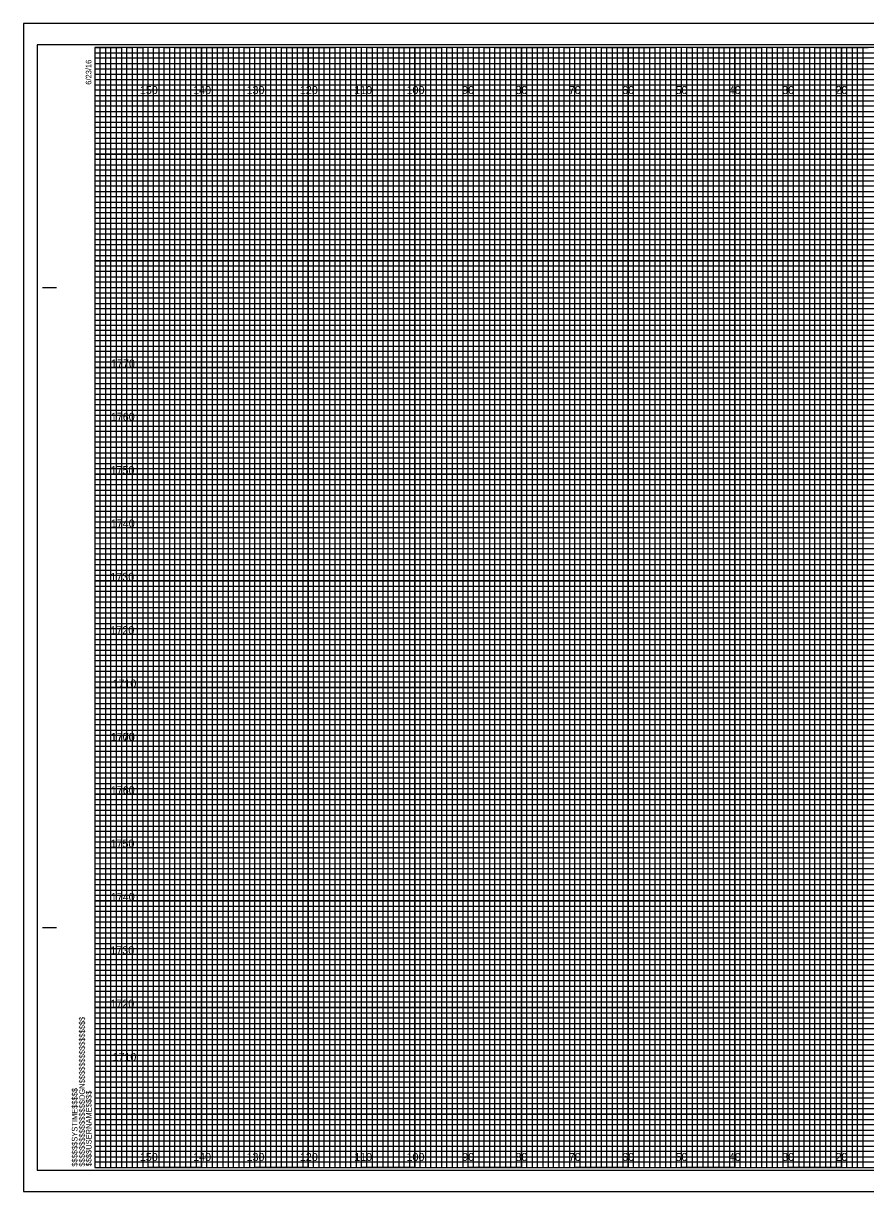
# Model space of a CAD drawing. Extents: x -419 to 4739, y -630 to 13534.
# Drawn here: x 476.2 to 634.1, y 4608 to 4827 of the extents above; entities that cross this region are included whole.
import ezdxf

# ---------------------------------------------------------------- set-up
doc = ezdxf.new("R2010")
doc.units = 0
for name, color, linetype in [('Old_Level_62', 7, 'Continuous'), ('Pattern 1', 7, 'Continuous'), ('Pattern 18', 7, 'Continuous'), ('Pattern 4', 7, 'Continuous'), ('Pattern 5', 7, 'Continuous'), ('Prop Dimension', 7, 'Continuous'), ('Prop Horizontal Alignment', 7, 'Continuous'), ('Raster_Level_0', 7, 'Continuous'), ('Scratch_Level_0', 7, 'Continuous'), ('Scratch_Level_3', 7, 'Continuous'), ('Scratch_Level_5', 7, 'Continuous')]:
    doc.layers.add(name, color=color, linetype=linetype)

msp = doc.modelspace()

# ---------------------------------------------------------------- linework, layer by layer
at = {"layer": 'Old_Level_62'}
for p, q in [((479.78, 4777.54), (482.28, 4777.54)), ((479.88, 4777.54), (482.38, 4777.54)), ((479.78, 4657.54), (482.28, 4657.54)), ((479.88, 4657.54), (482.38, 4657.54)), ((489.58, 4612.54), (489.58, 4612.54)), ((489.58, 4612.54), (489.58, 4612.54)), ((489.58, 4612.54), (489.58, 4612.54)), ((489.58, 4612.54), (489.58, 4612.54)), ((489.58, 4612.54), (489.58, 4612.54)), ((489.58, 4612.54), (489.58, 4612.54)), ((489.58, 4612.54), (489.58, 4612.54))]:
    msp.add_line(p, q, dxfattribs=at)
msp.add_lwpolyline([(809.58, 4822.54), (489.58, 4822.54), (489.58, 4612.54), (809.58, 4612.54)], close=True, dxfattribs=at)
at = {"layer": 'Pattern 18'}
msp.add_lwpolyline([(476.18, 4608.04), (812.88, 4608.04), (812.88, 4827.04), (476.18, 4827.04)], close=True, dxfattribs=at)
at = {"layer": 'Pattern 4'}
for p, q in [((489.58, 4821.54), (749.58, 4821.54)), ((749.58, 4820.52), (489.58, 4820.52)), ((489.58, 4820.52), (489.58, 4819.54)), ((489.58, 4819.54), (749.58, 4819.54)), ((749.58, 4818.43), (489.58, 4818.43)), ((489.58, 4818.43), (489.58, 4816.54)), ((489.58, 4816.54), (809.58, 4816.54))]:
    msp.add_line(p, q, dxfattribs=at)
for points in [[(489.58, 4815.54), (759.58, 4815.54), (809.58, 4815.54), (809.58, 4814.54), (489.58, 4814.54)], [(489.58, 4813.54), (809.58, 4813.54), (809.58, 4811.54), (489.58, 4811.54)], [(489.58, 4810.54), (809.58, 4810.54), (809.58, 4809.54), (489.58, 4809.52)], [(489.58, 4808.54), (809.58, 4808.54), (809.58, 4806.54), (489.58, 4806.54)], [(489.58, 4805.54), (809.58, 4805.54), (809.58, 4804.54), (489.58, 4804.54)], [(489.58, 4803.54), (809.58, 4803.54), (809.58, 4801.54), (489.58, 4801.54)], [(489.58, 4800.54), (809.58, 4800.54), (809.58, 4799.54), (489.58, 4799.54)], [(489.58, 4798.54), (809.58, 4798.54), (809.58, 4796.54), (489.58, 4796.54)], [(489.58, 4795.54), (809.58, 4795.54), (809.58, 4794.54), (489.58, 4794.54)], [(489.58, 4793.54), (809.58, 4793.54), (809.58, 4791.54), (489.58, 4791.54)], [(489.58, 4790.54), (809.58, 4790.54), (809.58, 4789.54), (489.58, 4789.54)], [(489.58, 4788.54), (809.58, 4788.54), (809.58, 4786.49), (809.58, 4785.54), (809.58, 4784.54), (489.58, 4784.54)], [(489.58, 4786.54), (809.58, 4786.54), (809.58, 4785.54), (489.58, 4785.54)], [(489.58, 4783.54), (809.58, 4783.54), (809.58, 4781.54), (489.58, 4781.57)], [(489.58, 4781.57), (809.58, 4781.54), (809.58, 4780.54), (489.58, 4780.54)], [(489.58, 4779.54), (809.58, 4779.54), (809.58, 4778.54), (489.58, 4778.54)], [(489.58, 4776.54), (809.58, 4776.54), (809.58, 4775.54), (489.58, 4775.54)], [(489.58, 4774.54), (809.58, 4774.54), (809.58, 4773.54), (489.58, 4773.54)], [(489.51, 4771.43), (809.58, 4771.43), (809.58, 4770.42), (489.51, 4770.42)], [(489.58, 4769.54), (809.58, 4769.54), (809.58, 4768.54), (489.58, 4768.54)], [(489.58, 4766.54), (809.58, 4766.54), (809.58, 4765.54), (489.58, 4765.54)], [(489.58, 4764.54), (809.58, 4764.54), (809.58, 4763.54), (489.58, 4763.54)], [(489.58, 4761.54), (809.58, 4761.54), (809.58, 4760.54), (489.58, 4760.54)], [(489.58, 4759.54), (809.58, 4759.54), (809.58, 4758.54), (489.58, 4758.54)], [(489.58, 4756.54), (809.58, 4756.54), (809.58, 4755.54), (489.58, 4755.54)], [(489.58, 4754.54), (809.58, 4754.54), (809.58, 4753.54), (489.58, 4753.54)], [(489.58, 4751.54), (809.58, 4751.54), (809.57, 4750.52), (489.58, 4750.54)], [(489.58, 4749.54), (809.58, 4749.54), (809.58, 4748.54), (489.58, 4748.54)], [(489.58, 4746.54), (809.58, 4746.54), (809.58, 4745.54), (489.58, 4745.54)], [(489.58, 4744.54), (809.58, 4744.54), (809.58, 4743.54), (489.58, 4743.54)], [(489.58, 4741.54), (809.58, 4741.54), (809.58, 4740.54), (489.58, 4740.54)], [(489.58, 4739.54), (809.58, 4739.54), (809.58, 4738.54), (489.58, 4738.54)], [(489.58, 4736.54), (809.58, 4736.54), (809.58, 4735.54), (489.58, 4735.54)], [(489.58, 4734.54), (809.58, 4734.54), (809.58, 4733.54), (489.58, 4733.54)], [(489.58, 4731.54), (809.58, 4731.54), (809.58, 4730.54), (489.58, 4730.54)], [(489.58, 4729.53), (809.65, 4729.45), (809.58, 4728.54), (489.58, 4728.54)], [(489.58, 4726.54), (809.58, 4726.54), (809.58, 4725.54), (489.58, 4725.54)], [(489.58, 4724.54), (809.58, 4724.54), (809.58, 4723.54), (489.58, 4723.54)], [(489.58, 4721.54), (809.58, 4721.54), (809.58, 4720.54), (489.58, 4720.54)], [(489.58, 4719.54), (809.58, 4719.54), (809.58, 4718.54), (489.58, 4718.54)], [(489.58, 4716.54), (809.58, 4716.54), (809.58, 4715.54), (489.58, 4715.54)], [(489.58, 4714.54), (809.58, 4714.54), (809.58, 4713.54), (489.58, 4713.54)], [(489.58, 4711.54), (809.58, 4711.54), (809.58, 4710.54), (489.58, 4710.54)], [(489.58, 4709.54), (809.58, 4709.54), (809.58, 4708.54), (489.58, 4708.54)], [(489.58, 4706.54), (809.58, 4706.54), (809.58, 4705.54), (489.58, 4705.54)], [(489.58, 4704.54), (809.58, 4704.54), (809.58, 4703.54), (489.58, 4703.54)], [(489.58, 4701.54), (809.58, 4701.54), (809.58, 4700.54), (489.58, 4700.54)], [(489.58, 4699.54), (809.58, 4699.54), (809.58, 4698.54), (489.58, 4698.54)], [(489.58, 4696.54), (809.58, 4696.54), (809.58, 4695.54), (489.58, 4695.54)], [(489.58, 4694.54), (809.58, 4694.54), (809.58, 4693.54), (489.58, 4693.54)], [(489.58, 4691.54), (809.58, 4691.54), (809.57, 4690.52), (489.58, 4690.54)], [(489.58, 4689.54), (809.58, 4689.54), (809.58, 4688.54), (489.58, 4688.54)], [(489.58, 4686.54), (809.58, 4686.54), (809.58, 4685.54), (489.58, 4685.54)], [(489.58, 4684.54), (809.58, 4684.54), (809.58, 4683.54), (489.58, 4683.54)], [(489.58, 4681.54), (809.58, 4681.54), (809.58, 4680.54), (489.58, 4680.54)], [(489.58, 4679.54), (809.58, 4679.54), (809.58, 4678.54), (489.58, 4678.54)], [(489.58, 4676.54), (809.58, 4676.54), (809.58, 4675.54), (489.58, 4675.54)], [(489.58, 4674.54), (809.58, 4674.54), (809.58, 4673.54), (489.58, 4673.54)], [(489.58, 4671.54), (809.58, 4671.54), (809.58, 4670.54), (489.58, 4670.54)], [(489.58, 4669.53), (809.65, 4669.45), (809.58, 4668.54), (489.58, 4668.54)], [(489.58, 4666.54), (809.58, 4666.54), (809.58, 4665.54), (489.58, 4665.54)], [(489.58, 4664.54), (809.58, 4664.54), (809.58, 4663.54), (489.58, 4663.54)], [(489.58, 4661.54), (809.58, 4661.54), (809.58, 4660.54), (489.58, 4660.54)], [(489.58, 4659.54), (809.58, 4659.54), (809.58, 4658.54), (489.58, 4658.54)], [(489.58, 4656.54), (809.58, 4656.54), (809.58, 4655.54), (489.58, 4655.54)], [(489.58, 4654.54), (809.58, 4654.54), (809.58, 4653.54), (489.58, 4653.54)], [(489.58, 4651.54), (809.58, 4651.54), (809.58, 4650.54), (489.58, 4650.54)], [(489.58, 4649.54), (809.58, 4649.54), (809.58, 4648.54), (489.58, 4648.54)], [(489.58, 4646.54), (809.58, 4646.54), (809.58, 4645.54), (489.58, 4645.54)], [(489.58, 4644.54), (809.58, 4644.54), (809.58, 4643.54), (489.58, 4643.54)], [(489.58, 4641.54), (809.58, 4641.54), (809.58, 4640.54), (489.58, 4640.54)], [(489.58, 4639.54), (809.58, 4639.54), (809.58, 4638.54), (489.58, 4638.54)], [(489.58, 4636.54), (809.58, 4636.54), (809.58, 4635.54), (489.58, 4635.54)], [(489.58, 4634.54), (809.58, 4634.54), (809.58, 4633.54), (489.58, 4633.54)], [(489.58, 4631.54), (809.58, 4631.54), (809.58, 4630.54), (489.58, 4630.54)], [(489.58, 4629.54), (809.58, 4629.54), (809.58, 4628.54), (489.58, 4628.54)], [(489.58, 4626.54), (809.58, 4626.54), (809.58, 4625.54), (489.58, 4625.54)], [(489.58, 4624.54), (809.58, 4624.54), (809.58, 4623.54), (489.58, 4623.54)], [(489.58, 4621.54), (809.58, 4621.54), (809.58, 4620.54), (489.58, 4620.54)], [(489.58, 4619.54), (809.58, 4619.54), (809.58, 4618.54), (489.58, 4618.54)], [(489.58, 4616.54), (809.58, 4616.54), (809.58, 4615.54), (489.58, 4615.54)], [(489.58, 4614.54), (809.58, 4614.54), (809.58, 4613.54), (489.58, 4613.54)]]:
    msp.add_lwpolyline(points, dxfattribs=at)
at = {"layer": 'Pattern 5'}
for p, q in [((812.88, 4827.04), (476.18, 4827.04)), ((476.18, 4827.04), (476.18, 4608.04)), ((476.18, 4608.04), (812.88, 4608.04))]:
    msp.add_line(p, q, dxfattribs=at)
at = {"layer": 'Prop Dimension'}
for points in [[(489.58, 4612.54), (490.58, 4612.54), (490.58, 4822.54), (491.58, 4822.54), (491.58, 4612.54)], [(491.58, 4612.54), (492.58, 4612.54), (492.58, 4822.54), (493.58, 4822.54), (493.58, 4612.54)], [(494.58, 4612.54), (495.58, 4612.54), (495.58, 4822.54), (496.58, 4822.54), (496.58, 4612.54)], [(496.58, 4612.54), (497.58, 4612.54), (497.58, 4822.54), (498.58, 4822.54), (498.58, 4612.54)], [(499.58, 4612.54), (500.58, 4612.54), (500.58, 4822.54), (501.58, 4822.54), (501.58, 4612.54)], [(501.58, 4612.54), (502.58, 4612.54), (502.58, 4822.54), (503.58, 4822.54), (503.58, 4612.54)], [(504.58, 4612.54), (505.58, 4612.54), (505.58, 4822.54), (506.58, 4822.54), (506.58, 4612.54)], [(506.58, 4612.54), (507.58, 4612.54), (507.58, 4822.54), (508.58, 4822.54), (508.58, 4612.54)], [(509.58, 4612.54), (510.58, 4612.54), (510.58, 4822.54), (511.58, 4822.54), (511.58, 4612.54)], [(511.58, 4612.54), (512.58, 4612.54), (512.58, 4822.54), (513.58, 4822.54), (513.58, 4612.54)], [(514.58, 4612.54), (515.58, 4612.54), (515.58, 4822.54), (516.58, 4822.54), (516.58, 4612.54)], [(516.58, 4612.54), (517.58, 4612.54), (517.58, 4822.54), (518.58, 4822.54), (518.58, 4612.54)], [(519.58, 4612.54), (520.58, 4612.54), (520.58, 4822.54), (521.58, 4822.54), (521.58, 4612.54)], [(521.58, 4612.54), (522.58, 4612.54), (522.58, 4822.54), (523.58, 4822.54), (523.58, 4612.54)], [(524.58, 4612.54), (525.58, 4612.54), (525.58, 4822.54), (526.58, 4822.54), (526.58, 4612.54)], [(526.58, 4612.54), (527.58, 4612.54), (527.58, 4822.54), (528.58, 4822.54), (528.58, 4612.54)], [(529.58, 4612.54), (530.58, 4612.54), (530.58, 4822.54), (531.58, 4822.54), (531.58, 4612.54)], [(531.58, 4612.54), (532.58, 4612.54), (532.58, 4822.54), (533.58, 4822.54), (533.58, 4612.54)], [(534.58, 4612.54), (535.58, 4612.54), (535.58, 4822.54), (536.58, 4822.54), (536.58, 4612.54)], [(536.58, 4612.54), (537.58, 4612.54), (537.58, 4822.54), (538.58, 4822.54), (538.58, 4612.54)], [(539.58, 4612.54), (540.58, 4612.54), (540.58, 4822.54), (541.58, 4822.54), (541.58, 4612.54)], [(541.58, 4612.54), (542.58, 4612.54), (542.58, 4822.54), (543.58, 4822.54), (543.58, 4612.54)], [(544.58, 4612.54), (545.58, 4612.54), (545.58, 4822.54), (546.58, 4822.54), (546.58, 4612.54)], [(546.58, 4612.54), (547.58, 4612.54), (547.58, 4822.54), (548.58, 4822.54), (548.58, 4612.54)], [(549.58, 4612.54), (550.58, 4612.54), (550.58, 4822.54), (551.58, 4822.54), (551.58, 4612.54)], [(551.58, 4612.54), (552.58, 4612.54), (552.58, 4822.54), (553.58, 4822.54), (553.58, 4612.54)], [(554.58, 4612.54), (555.58, 4612.54), (555.58, 4822.54), (556.58, 4822.54), (556.58, 4612.54)], [(556.58, 4612.54), (557.58, 4612.54), (557.58, 4822.54), (558.58, 4822.54), (558.58, 4612.54)], [(559.58, 4612.54), (560.58, 4612.54), (560.58, 4822.54), (561.58, 4822.54), (561.58, 4612.54)], [(561.58, 4612.54), (562.58, 4612.54), (562.58, 4822.54), (563.58, 4822.54), (563.58, 4612.54)], [(564.58, 4612.54), (565.58, 4612.54), (565.58, 4822.54), (566.58, 4822.54), (566.58, 4612.54)], [(566.58, 4612.54), (567.58, 4612.54), (567.58, 4822.54), (568.58, 4822.54), (568.58, 4612.54)], [(569.58, 4612.54), (570.58, 4612.54), (570.58, 4822.54), (571.58, 4822.54), (571.58, 4612.54)], [(571.58, 4612.54), (572.58, 4612.54), (572.58, 4822.54), (573.58, 4822.54), (573.58, 4612.54)], [(574.58, 4612.54), (575.58, 4612.54), (575.58, 4822.54), (576.58, 4822.54), (576.58, 4612.54)], [(576.58, 4612.54), (577.58, 4612.54), (577.58, 4822.54), (578.58, 4822.54), (578.58, 4612.54)], [(579.58, 4612.54), (580.58, 4612.54), (580.58, 4822.54), (581.58, 4822.54), (581.58, 4612.54)], [(581.58, 4612.54), (582.58, 4612.54), (582.58, 4822.54), (583.58, 4822.54), (583.58, 4612.54)], [(584.58, 4612.54), (585.58, 4612.54), (585.58, 4822.54), (586.58, 4822.54), (586.58, 4612.54)], [(586.58, 4612.54), (587.58, 4612.54), (587.58, 4822.54), (588.58, 4822.54), (588.58, 4612.54)], [(589.58, 4612.54), (590.58, 4612.54), (590.58, 4822.54), (591.58, 4822.54), (591.58, 4612.54)], [(591.58, 4612.54), (592.58, 4612.54), (592.58, 4822.54), (593.58, 4822.54), (593.58, 4612.54)], [(594.58, 4612.54), (595.58, 4612.54), (595.58, 4822.54), (596.58, 4822.54), (596.58, 4612.54)], [(596.58, 4612.54), (597.58, 4612.54), (597.58, 4822.54), (598.58, 4822.54), (598.58, 4612.54)], [(599.58, 4612.54), (600.58, 4612.54), (600.58, 4822.54), (601.58, 4822.54), (601.58, 4612.54)], [(601.58, 4612.54), (602.58, 4612.54), (602.58, 4822.54), (603.58, 4822.54), (603.58, 4612.54)], [(604.58, 4612.54), (605.58, 4612.54), (605.58, 4822.54), (606.58, 4822.54), (606.58, 4612.54)], [(606.58, 4612.54), (607.58, 4612.54), (607.58, 4822.54), (608.58, 4822.54), (608.58, 4612.54)], [(609.58, 4612.54), (610.58, 4612.54), (610.58, 4822.54), (611.58, 4822.54), (611.58, 4612.54)], [(611.58, 4612.54), (612.58, 4612.54), (612.58, 4822.54), (613.58, 4822.54), (613.58, 4612.54)], [(614.58, 4612.54), (615.58, 4612.54), (615.58, 4822.54), (616.58, 4822.54), (616.58, 4612.54)], [(616.58, 4612.54), (617.58, 4612.54), (617.58, 4822.54), (618.58, 4822.54), (618.58, 4612.54)], [(619.58, 4612.54), (620.58, 4612.54), (620.58, 4822.54), (621.58, 4822.54), (621.58, 4612.54)], [(621.58, 4612.54), (622.58, 4612.54), (622.58, 4822.54), (623.58, 4822.54), (623.58, 4612.54)], [(624.58, 4612.54), (625.58, 4612.54), (625.58, 4822.54), (626.58, 4822.54), (626.58, 4612.54)], [(626.58, 4612.54), (627.58, 4612.54), (627.58, 4822.54), (628.58, 4822.54), (628.58, 4612.54)], [(629.58, 4612.54), (630.58, 4612.54), (630.58, 4822.54), (631.58, 4822.54), (631.58, 4612.54)], [(631.58, 4612.54), (632.58, 4612.54), (632.58, 4822.54), (633.58, 4822.54), (633.58, 4612.54)]]:
    msp.add_lwpolyline(points, dxfattribs=at)
at = {"layer": 'Prop Horizontal Alignment'}
for points in [[(489.58, 4822.54), (494.58, 4822.54), (494.58, 4612.54), (504.58, 4612.54), (504.58, 4822.54), (514.58, 4822.54), (514.58, 4612.54), (524.58, 4612.54), (524.58, 4822.54), (534.58, 4822.54), (534.58, 4612.54), (544.58, 4612.54), (544.58, 4822.54), (554.58, 4822.54), (554.58, 4612.54), (564.58, 4612.54), (564.58, 4822.54), (574.58, 4822.54), (574.58, 4612.54), (584.58, 4612.54), (584.58, 4822.54), (594.58, 4822.54), (594.58, 4612.54), (604.58, 4612.54), (604.58, 4822.54), (614.58, 4822.54), (614.58, 4612.54), (624.58, 4612.54), (624.58, 4822.54), (634.58, 4822.54)], [(489.58, 4817.54), (764.58, 4817.54)], [(489.58, 4797.54), (809.58, 4797.54), (809.58, 4807.54), (489.58, 4807.54)], [(489.58, 4777.54), (809.58, 4777.54), (809.58, 4787.54), (489.58, 4787.54)], [(489.58, 4757.54), (809.58, 4757.54), (809.58, 4767.54), (489.58, 4767.54)], [(489.58, 4737.54), (809.58, 4737.54), (809.58, 4747.54), (489.58, 4747.54)], [(489.58, 4717.54), (809.58, 4717.54), (809.58, 4727.54), (489.58, 4727.54)], [(489.58, 4697.54), (809.58, 4697.54), (809.58, 4707.54), (489.58, 4707.54)], [(489.58, 4677.54), (809.58, 4677.54), (809.58, 4687.54), (489.58, 4687.54)], [(489.58, 4657.54), (809.58, 4657.54), (809.58, 4667.54), (489.58, 4667.54)], [(489.58, 4637.54), (809.58, 4637.54), (809.58, 4647.54), (489.58, 4647.54)], [(489.58, 4617.54), (809.58, 4617.54), (809.58, 4627.54), (489.58, 4627.54)]]:
    msp.add_lwpolyline(points, dxfattribs=at)
at = {"layer": 'Scratch_Level_0'}
for p, q in [((499.58, 4612.54), (499.58, 4822.54)), ((509.58, 4612.54), (509.58, 4822.54)), ((519.58, 4612.54), (519.58, 4822.54)), ((529.58, 4612.54), (529.58, 4822.54)), ((539.58, 4612.54), (539.58, 4822.54)), ((549.58, 4612.54), (549.58, 4822.54)), ((559.58, 4612.54), (559.58, 4822.54)), ((569.58, 4612.54), (569.58, 4822.54)), ((579.58, 4612.54), (579.58, 4822.54)), ((589.58, 4612.54), (589.58, 4822.54)), ((599.58, 4612.54), (599.58, 4822.54)), ((609.58, 4612.54), (609.58, 4822.54)), ((619.58, 4612.54), (619.58, 4822.54)), ((629.58, 4612.54), (629.58, 4822.54)), ((489.58, 4812.54), (809.58, 4812.54)), ((489.58, 4802.54), (809.58, 4802.54)), ((489.58, 4792.54), (809.58, 4792.54)), ((489.58, 4782.54), (809.58, 4782.54)), ((489.58, 4772.54), (809.58, 4772.54)), ((489.58, 4762.54), (809.58, 4762.54)), ((489.58, 4752.54), (809.58, 4752.54)), ((489.58, 4742.54), (809.58, 4742.54)), ((489.58, 4732.54), (809.58, 4732.54)), ((489.58, 4722.54), (809.58, 4722.54)), ((489.58, 4712.54), (809.58, 4712.54)), ((489.58, 4702.54), (809.58, 4702.54)), ((489.58, 4692.54), (809.58, 4692.54)), ((489.58, 4682.54), (809.58, 4682.54)), ((489.58, 4672.54), (809.58, 4672.54)), ((489.58, 4662.54), (809.58, 4662.54)), ((489.58, 4652.54), (809.58, 4652.54)), ((489.58, 4642.54), (809.58, 4642.54)), ((489.58, 4632.54), (809.58, 4632.54)), ((489.58, 4622.54), (809.58, 4622.54))]:
    msp.add_line(p, q, dxfattribs=at)
at = {"layer": 'Scratch_Level_3'}
for p, q in [((499.58, 4822.54), (489.58, 4822.54)), ((499.58, 4612.54), (499.58, 4822.54)), ((519.58, 4822.54), (509.58, 4822.54)), ((509.58, 4822.54), (509.58, 4612.54)), ((519.58, 4612.54), (519.58, 4822.54)), ((539.58, 4822.54), (529.58, 4822.54)), ((529.58, 4822.54), (529.58, 4612.54)), ((539.58, 4612.54), (539.58, 4822.54)), ((559.58, 4822.54), (549.58, 4822.54)), ((549.58, 4822.54), (549.58, 4612.54)), ((559.58, 4612.54), (559.58, 4822.54)), ((579.58, 4822.54), (569.58, 4822.54)), ((569.58, 4822.54), (569.58, 4612.54)), ((579.58, 4612.54), (579.58, 4822.54)), ((599.58, 4822.54), (589.58, 4822.54)), ((589.58, 4822.54), (589.58, 4612.54)), ((599.58, 4612.54), (599.58, 4822.54)), ((619.58, 4822.54), (609.58, 4822.54)), ((609.58, 4822.54), (609.58, 4612.54)), ((619.58, 4612.54), (619.58, 4822.54)), ((639.58, 4822.54), (629.58, 4822.54)), ((629.58, 4822.54), (629.58, 4612.54)), ((509.58, 4612.54), (499.58, 4612.54)), ((529.58, 4612.54), (519.58, 4612.54)), ((549.58, 4612.54), (539.58, 4612.54)), ((569.58, 4612.54), (559.58, 4612.54)), ((589.58, 4612.54), (579.58, 4612.54)), ((609.58, 4612.54), (599.58, 4612.54)), ((629.58, 4612.54), (619.58, 4612.54))]:
    msp.add_line(p, q, dxfattribs=at)
for points in [[(489.58, 4812.54), (809.58, 4812.54), (809.58, 4802.54), (489.58, 4802.54)], [(489.58, 4792.54), (809.58, 4792.54), (809.58, 4782.54), (489.58, 4782.54)], [(489.58, 4772.54), (809.58, 4772.54), (809.58, 4762.54), (489.58, 4762.54)], [(489.58, 4752.54), (809.58, 4752.54), (809.58, 4742.54), (489.58, 4742.54)], [(489.58, 4732.54), (809.58, 4732.54), (809.58, 4722.54), (489.58, 4722.54)], [(489.58, 4712.54), (809.58, 4712.54), (809.58, 4702.54), (489.58, 4702.54)], [(489.58, 4692.54), (809.58, 4692.54), (809.58, 4682.54), (489.58, 4682.54)], [(489.58, 4672.54), (809.58, 4672.54), (809.58, 4662.54), (489.58, 4662.54)], [(489.58, 4652.54), (809.58, 4652.54), (809.58, 4642.54), (489.58, 4642.54)], [(489.58, 4632.54), (809.58, 4632.54), (809.58, 4622.54), (489.58, 4622.54)]]:
    msp.add_lwpolyline(points, dxfattribs=at)
at = {"layer": 'Scratch_Level_5'}
msp.add_lwpolyline([(478.78, 4612.04), (811.98, 4612.04), (811.98, 4823.04), (478.78, 4823.04)], close=True, dxfattribs=at)

# ---------------------------------------------------------------- texts
at = {"layer": 'Old_Level_62'}
for s, p in [('6/23/16', (488.93, 4815.54)), ('$$$$$$$$$$$$$$$$DGN$$$$$$$$$$$$$$$$', (487.7, 4612.72)), ('$$$$$$SYSTIME$$$$$', (486.32, 4612.72)), ('$$$$USERNAME$$$$', (488.96, 4612.77))]:
    msp.add_text(s, height=1.05, rotation=90, dxfattribs=at).set_placement(p)
at = {"layer": 'Pattern 1'}
for s, p in [('1770', (492.62, 4762.54)), ('1760', (492.58, 4752.54)), ('1750', (492.53, 4742.54)), ('1740', (492.58, 4732.54)), ('1730', (492.5, 4722.54)), ('1720', (492.51, 4712.54)), ('1710', (492.89, 4702.54)), ('1700', (492.56, 4692.54)), ('1770', (492.62, 4692.54)), ('1760', (492.58, 4682.54)), ('1750', (492.53, 4672.54)), ('1740', (492.58, 4662.54)), ('1730', (492.5, 4652.54)), ('1720', (492.51, 4642.54)), ('1710', (492.89, 4632.54))]:
    msp.add_text(s, height=1.5, dxfattribs=at).set_placement(p)
at = {"layer": 'Raster_Level_0'}
for s, p in [('150', (498.02, 4813.79)), ('140', (508.02, 4813.79)), ('130', (518.02, 4813.79)), ('120', (528.02, 4813.79)), ('110', (538.2, 4813.79)), ('100', (548.02, 4813.79)), ('90', (558.44, 4813.79)), ('80', (568.44, 4813.79)), ('70', (578.44, 4813.79)), ('60', (588.44, 4813.79)), ('50', (598.44, 4813.79)), ('40', (608.44, 4813.79)), ('30', (618.44, 4813.79)), ('20', (628.44, 4813.79)), ('150', (498.02, 4613.79)), ('140', (508.02, 4613.79)), ('130', (518.02, 4613.79)), ('120', (528.02, 4613.79)), ('110', (538.2, 4613.79)), ('100', (548.02, 4613.79)), ('90', (558.44, 4613.79)), ('80', (568.44, 4613.79)), ('70', (578.44, 4613.79)), ('60', (588.44, 4613.79)), ('50', (598.44, 4613.79)), ('40', (608.44, 4613.79)), ('30', (618.44, 4613.79)), ('20', (628.44, 4613.79))]:
    msp.add_text(s, height=1.5, dxfattribs=at).set_placement(p)

doc.saveas('drawing.dxf')
